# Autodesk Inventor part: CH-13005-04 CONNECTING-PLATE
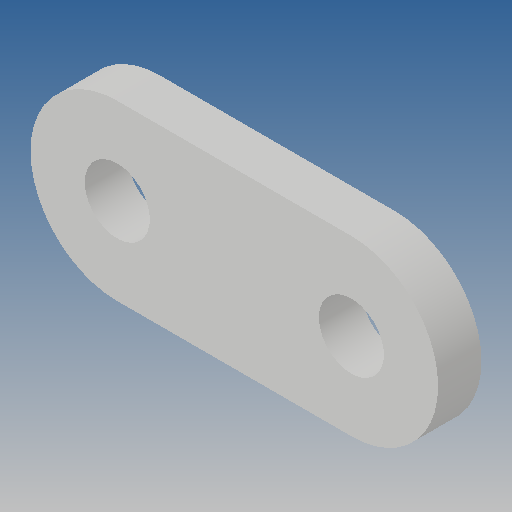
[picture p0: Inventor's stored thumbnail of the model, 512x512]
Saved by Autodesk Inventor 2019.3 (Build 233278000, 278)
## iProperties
Created: 2012-09
Part Number: CH-13005-04 CONNECTING-PLATE
Material: Ogólny
Document SubType Name: Modeling
Designer: CADENGINEERING4
Density: 1 g/cm^3
Appearance: Domyślna
Author: CADENGINEERING4
Revision Number: ÈÎºÎ
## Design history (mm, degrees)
feature "À­Éì1"
node "Bryła1"
